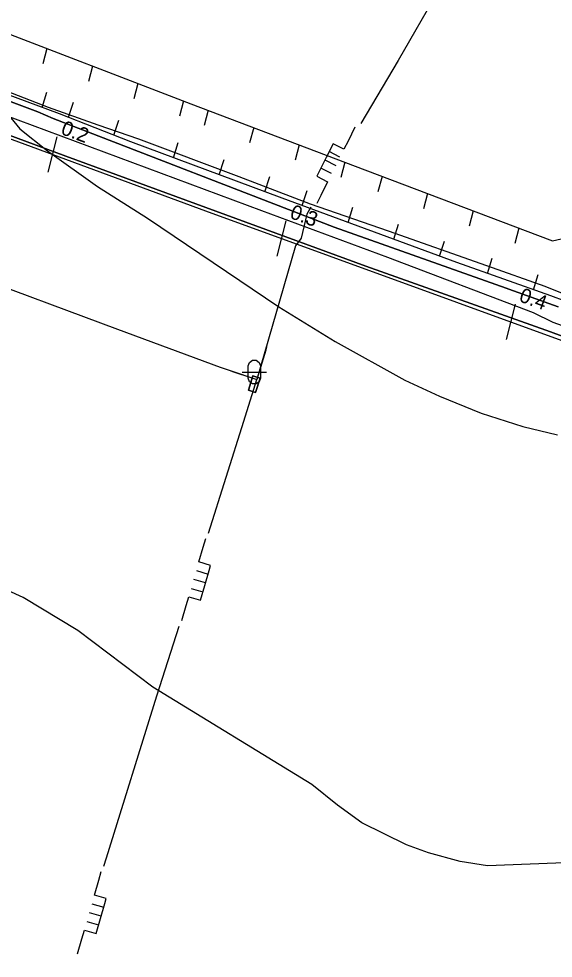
# Model space of a CAD drawing. Extents: x -645676 to -642474, y -1077513 to -1072613.
# Drawn here: x -643938.6 to -643719.5, y -1075467.2 to -1075082.2 of the extents above; entities that cross this region are included whole.
import ezdxf

# ---------------------------------------------------------------- set-up
doc = ezdxf.new("R2010")
doc.units = 0
for name, color, linetype in [('_elezni_n__tra_', 7, 'Continuous'), ('KULTURY_STAV', 7, 'Continuous'), ('KULTURY_ZNACKY', 7, 'Continuous'), ('PC_NAVRH', 7, 'Continuous'), ('PC_STAN_NAVRH', 7, 'Continuous'), ('PLYNOVOD', 7, 'Continuous'), ('SDELOVACI', 7, 'Continuous'), ('USES_BK_NAVRH', 7, 'Continuous'), ('VRSTEVNICE', 7, 'Continuous'), ('Vrstevnice_zd_razn_n_', 7, 'Continuous')]:
    doc.layers.add(name, color=color, linetype=linetype)

# ---------------------------------------------------------------- blocks, each defined once
blk = doc.blocks.new('$944')
blk.add_line((0, 1.5), (0, -1.5))
blk = doc.blocks.new('3$1600')
for points in [[(-0.5, 1.5), (-0.4, 1.79), (-0.15, 1.97), (0.16, 1.97), (0.41, 1.79), (0.51, 1.5), (0.51, 0.5), (0.41, 0.21), (0.16, 0.03), (-0.15, 0.03), (-0.4, 0.21), (-0.5, 0.5), (-0.5, 1.5)], [(-1, 1), (0.27, 1), (1, 1)]]:
    blk.add_lwpolyline(points)
blk = doc.blocks.new('2$1030')
blk.add_line((0, 0), (0, -0.5))
blk = doc.blocks.new('6$3520')
for p, q in [((-0.76, 0), (-0.76, -1)), ((0, -1), (0, 0)), ((0.76, 0), (0.76, -1))]:
    blk.add_line(p, q)
blk.add_lwpolyline([(-3.5, 0), (-2.23, 0), (-1.48, 0), (-1.48, -1), (-0.21, -1), (1.06, -1), (1.5, -1), (1.5, 0), (2.77, 0), (3.5, 0)])

msp = doc.modelspace()

# ---------------------------------------------------------------- linework, layer by layer
at = {"layer": '_elezni_n__tra_'}
msp.add_lwpolyline([(-644073.62, -1075073.69), (-644009.64, -1075097.37), (-643839.2, -1075160.83), (-643787.5, -1075179.88), (-643727.73, -1075202.65), (-643719.69, -1075206.5), (-643676.68, -1075221.97)], dxfattribs=at)
at = {"layer": 'KULTURY_STAV'}
for points in [[(-643575.29, -1075264.44), (-643720.69, -1075210.59), (-643796.31, -1075183.6), (-643919.33, -1075138.53), (-643996.18, -1075110.11), (-644007.12, -1075105.96), (-644043.56, -1075092.84), (-644060.01, -1075086.39), (-644108.94, -1075067.42)], [(-644054.65, -1075074.74), (-644018.61, -1075087.61), (-643930.86, -1075120.34), (-643924.61, -1075123.03), (-643809.29, -1075167.61), (-643738.88, -1075192.66), (-643737.72, -1075193.07), (-643717.58, -1075200.24)], [(-643717.58, -1075200.24), (-643737.72, -1075193.07), (-643738.88, -1075192.66), (-643809.29, -1075167.61), (-643924.61, -1075123.03), (-643930.86, -1075120.34), (-644018.61, -1075087.61), (-644054.65, -1075074.74)], [(-644103.57, -1075083.11), (-644078.01, -1075085.28), (-644076.83, -1075085.54), (-644043.56, -1075092.84), (-644007.12, -1075105.96), (-643996.18, -1075110.11), (-643919.33, -1075138.53), (-643796.31, -1075183.6), (-643720.69, -1075210.59), (-643575.29, -1075264.44)], [(-643842.63, -1075228.62), (-643839.65, -1075229.54), (-643841.55, -1075235.39), (-643844.49, -1075234.46), (-643842.63, -1075228.62)], [(-643842.63, -1075228.62), (-643844.49, -1075234.46), (-643841.55, -1075235.39), (-643839.65, -1075229.54), (-643842.63, -1075228.62)]]:
    msp.add_lwpolyline(points, dxfattribs=at)
at = {"layer": 'PC_NAVRH'}
msp.add_lwpolyline([(-644115.89, -1075090.04), (-644061.03, -1075087.73), (-643984.83, -1075115.73), (-643862.1, -1075160.96), (-643708.49, -1075216.75), (-643576.12, -1075265.87), (-643454.04, -1075308.27)], dxfattribs=at)
at = {"layer": 'PLYNOVOD'}
for points in [[(-643717.01, -1074984.48), (-643783.07, -1075099.35), (-643798.43, -1075125.12)], [(-643818.91, -1075159.48), (-643820.57, -1075162.27), (-643822.94, -1075172.16), (-643825.2, -1075175.31), (-643841.02, -1075230.1)], [(-643963.86, -1075185.02), (-643962.1, -1075185.68), (-643898.17, -1075209.37), (-643856.07, -1075225.06), (-643851.99, -1075226.44), (-643841.02, -1075230.1)], [(-643840.57, -1075228.58), (-643837.2, -1075217.97), (-643836.89, -1075216.72)], [(-643851.99, -1075226.44), (-643850.98, -1075226.79), (-643843.15, -1075229.43)], [(-643860.86, -1075292.98), (-643846.37, -1075247.19), (-643841.02, -1075230.1)], [(-643903.75, -1075429.49), (-643902.71, -1075426.14), (-643881.98, -1075359.72), (-643872.93, -1075331.12)]]:
    msp.add_lwpolyline(points, dxfattribs=at)
at = {"layer": 'SDELOVACI'}
msp.add_lwpolyline([(-643682.9, -1075207.99), (-643722.89, -1075191.92), (-643746.72, -1075183.52), (-643787.04, -1075169.33), (-643819.03, -1075158.15), (-643848.29, -1075147), (-643889.38, -1075131.57), (-643906.06, -1075125.78), (-643926.44, -1075118.64), (-643969.07, -1075102.01), (-644002.79, -1075089.11), (-644042.73, -1075074.42)], dxfattribs=at)
at = {"layer": 'USES_BK_NAVRH'}
for points in [[(-644006.37, -1075487), (-644025.33, -1075415.58), (-644028.72, -1075402.04), (-644033.86, -1075390.28), (-644039.21, -1075371.01), (-644039.79, -1075365.47), (-644053.88, -1075317.15), (-644065.85, -1075276.41), (-644079.54, -1075229.6), (-644088.6, -1075196.48), (-644090.84, -1075189.07), (-644101.09, -1075154.48), (-644108.17, -1075128.15), (-644059.26, -1075087.42), (-644053.78, -1075048.2), (-643952.8, -1075084.61), (-643868.04, -1075117.09), (-643796.75, -1075144.16), (-643719.82, -1075173.18), (-643625.49, -1075151.66)], [(-643655.91, -1075219.78), (-643720.5, -1075195.81), (-643759.1, -1075182.13), (-643830.69, -1075155.72), (-643892.72, -1075132.68), (-643922, -1075121.15), (-643961.91, -1075106.43), (-643996.63, -1075093.94), (-644017.66, -1075086.4), (-644036.79, -1075098.78), (-644074.82, -1075138.63), (-644024.54, -1075322.4), (-643980.59, -1075469.44)]]:
    msp.add_lwpolyline(points, dxfattribs=at)
at = {"layer": 'VRSTEVNICE'}
for points in [[(-644024.83, -1075078.45), (-643996.35, -1075088.7), (-643976.41, -1075098.39), (-643953.34, -1075111.35), (-643948.21, -1075115.34), (-643938.24, -1075127.3), (-643926.85, -1075136.41), (-643906.34, -1075150.94), (-643885.83, -1075163.9), (-643831.99, -1075200.22), (-643808.92, -1075214.46), (-643780.44, -1075230.27), (-643766.19, -1075236.96), (-643749.1, -1075243.8), (-643732.01, -1075249.35), (-643717.77, -1075252.77)], [(-643818.5, -1075396.08), (-643883.69, -1075356.17), (-643914.45, -1075332.96), (-643936.82, -1075319.43), (-643952.77, -1075312.16), (-643988.66, -1075298.63), (-644016.29, -1075285.1), (-644029.67, -1075279.4), (-644056.02, -1075270.72), (-644059.06, -1075270.6)], [(-643618.61, -1075420.53), (-643634.58, -1075421.07), (-643675.13, -1075422.81), (-643711.48, -1075428.02), (-643746.49, -1075429.35), (-643757.68, -1075427.59), (-643770.71, -1075424.11), (-643779.69, -1075420.78), (-643797.94, -1075411.8), (-643808.04, -1075404.58), (-643818.5, -1075396.09)]]:
    msp.add_lwpolyline(points, dxfattribs=at)
at = {"layer": 'Vrstevnice_zd_razn_n_'}
msp.add_line((-643818.5, -1075396.09), (-643818.5, -1075396.08), dxfattribs=at)

# ---------------------------------------------------------------- block references
at = {"layer": 'KULTURY_ZNACKY', "xscale": 5, "yscale": 5}
msp.add_blockref('3$1600', (-643842.08, -1075232.01), dxfattribs=at)
at = {"layer": 'PC_STAN_NAVRH', "xscale": 5}
for p, yscale, rotation in [((-643924.86, -1075137.83), 4.999999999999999, -14.30020000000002), ((-643830.98, -1075172.26), 5, -14.026199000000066), ((-643736.99, -1075206.4), 5, -14.026199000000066)]:
    msp.add_blockref('$944', p, dxfattribs=dict(at, yscale=yscale, rotation=rotation))
at = {"layer": 'PLYNOVOD'}
for p, xscale, yscale, rotation in [((-643808.67, -1075142.3), 5, 5.000000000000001, -116.61980700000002), ((-643866.89, -1075312.05), 5, 5.000000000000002, 73.704375), ((-643909.69, -1075448.59), 4.999999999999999, 5, 74.002824)]:
    msp.add_blockref('6$3520', p, dxfattribs=dict(at, xscale=xscale, yscale=yscale, rotation=rotation))
at = {"layer": 'USES_BK_NAVRH'}
for p, xscale, yscale, rotation in [((-643927.12, -1075094.45), 13, 13, -15.053543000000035), ((-643908.44, -1075101.61), 13, 13, -15.053543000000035), ((-643889.77, -1075108.76), 13, 13, -15.053543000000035), ((-643929.03, -1075118.56), 13, 13, 162.534963), ((-643918.31, -1075122.61), 13, 12.999999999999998, 161.272716), ((-643871.09, -1075115.92), 13, 13, -15.053543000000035), ((-643861.03, -1075119.75), 13, 13, -14.87032900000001), ((-643899.7, -1075129.94), 13, 12.999999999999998, 161.272716), ((-643842.33, -1075126.85), 13, 13, -14.87032900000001), ((-643875.22, -1075139.18), 12.999999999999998, 13.000000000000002, 162.411598), ((-643823.63, -1075133.95), 13, 13, -14.87032900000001), ((-643856.47, -1075146.15), 12.999999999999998, 13.000000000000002, 162.411598), ((-643804.93, -1075141.05), 13, 13, -14.87032900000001), ((-643837.72, -1075153.11), 12.999999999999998, 13.000000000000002, 162.411598), ((-643789.73, -1075146.81), 13, 13.000000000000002, -14.750159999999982), ((-643822.43, -1075158.77), 12.999999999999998, 13, 162.536923), ((-643771.02, -1075153.87), 13, 13.000000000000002, -14.750159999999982), ((-643803.66, -1075165.69), 12.999999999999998, 13, 162.536923), ((-643752.31, -1075160.93), 13, 13.000000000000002, -14.750159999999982), ((-643784.9, -1075172.61), 12.999999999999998, 13, 162.536923), ((-643733.6, -1075167.99), 13, 13.000000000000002, -14.750159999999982), ((-643766.13, -1075179.54), 12.999999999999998, 13, 162.536923), ((-643746.42, -1075186.63), 13, 13, 163.28362199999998), ((-643727.57, -1075193.31), 13, 13, 163.28362199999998)]:
    msp.add_blockref('2$1030', p, dxfattribs=dict(at, xscale=xscale, yscale=yscale, rotation=rotation))

# ---------------------------------------------------------------- texts
at = {"layer": 'PC_STAN_NAVRH'}
for s, rotation, p in [('0.2', 339.764, (-643921.76, -1075129.38)), ('0.3', 340.05, (-643827.91, -1075163.8)), ('0.4', 340.05, (-643733.92, -1075197.93))]:
    msp.add_text(s, height=6, rotation=rotation, dxfattribs=at).set_placement(p)

doc.saveas('drawing.dxf')
